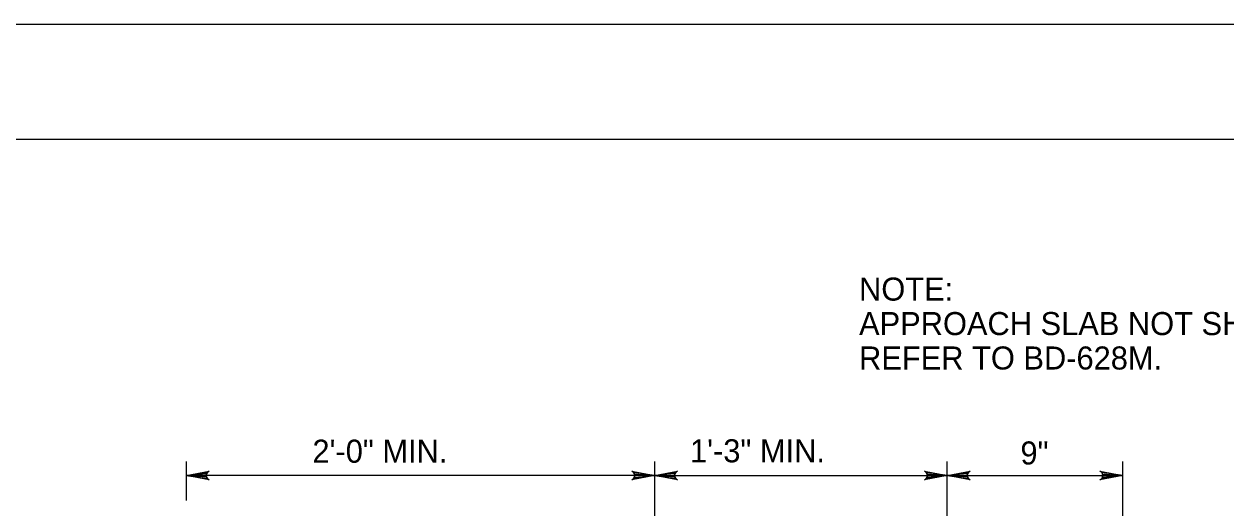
# Model space of a CAD drawing. Extents: x 640009 to 641706, y 298547 to 299735.
# Drawn here: x 640964.7 to 641121.1, y 299672.2 to 299735.2 of the extents above; entities that cross this region are included whole.
import ezdxf

# ---------------------------------------------------------------- set-up
doc = ezdxf.new("R2010")
doc.units = 0
doc.layers.add('1', color=7, linetype='Continuous')
doc.layers.add('PLT-BNDY', color=7, linetype='Continuous')

msp = doc.modelspace()

# ---------------------------------------------------------------- linework, layer by layer
at = {"layer": '1'}
for p, q in [((640890.47, 299720.17), (641676.47, 299720.17)), ((640890.47, 299720.17), (641676.47, 299720.17)), ((640985.78, 299678.22), (640985.78, 299673.16)), ((641046.74, 299678.22), (641046.74, 299655.13)), ((641084.84, 299649.2), (641084.84, 299678.22)), ((641107.7, 299669.52), (641107.7, 299678.22)), ((641046.74, 299676.42), (640985.78, 299676.42)), ((641046.74, 299676.42), (641084.84, 299676.42)), ((641084.84, 299676.42), (641107.7, 299676.42))]:
    msp.add_line(p, q, dxfattribs=at)
for points in [[(640985.78, 299676.42), (640988.77, 299676.98), (640988.54, 299676.82), (640988.42, 299676.62), (640988.38, 299676.42), (640988.42, 299676.22), (640988.54, 299676.02), (640988.77, 299675.86), (640985.78, 299676.42), (640988.54, 299676.02), (640988.42, 299676.22), (640985.78, 299676.42), (640988.38, 299676.42), (640988.42, 299676.62), (640985.78, 299676.42), (640988.54, 299676.82)], [(641046.74, 299676.42), (641043.76, 299675.86), (641043.99, 299676.02), (641044.11, 299676.22), (641044.14, 299676.42), (641044.11, 299676.62), (641043.99, 299676.82), (641043.76, 299676.98), (641046.74, 299676.42), (641043.99, 299676.82), (641044.11, 299676.62), (641046.74, 299676.42), (641044.14, 299676.42), (641044.11, 299676.22), (641046.74, 299676.42), (641043.99, 299676.02)], [(641046.74, 299676.42), (641049.73, 299676.98), (641049.5, 299676.82), (641049.38, 299676.62), (641049.34, 299676.42), (641049.38, 299676.22), (641049.5, 299676.02), (641049.73, 299675.86), (641046.74, 299676.42), (641049.5, 299676.02), (641049.38, 299676.22), (641046.74, 299676.42), (641049.34, 299676.42), (641049.38, 299676.62), (641046.74, 299676.42), (641049.5, 299676.82)], [(641084.84, 299676.42), (641081.86, 299675.86), (641082.09, 299676.02), (641082.21, 299676.22), (641082.24, 299676.42), (641082.21, 299676.62), (641082.09, 299676.82), (641081.86, 299676.98), (641084.84, 299676.42), (641082.09, 299676.82), (641082.21, 299676.62), (641084.84, 299676.42), (641082.24, 299676.42), (641082.21, 299676.22), (641084.84, 299676.42), (641082.09, 299676.02)], [(641084.84, 299676.42), (641087.83, 299676.98), (641087.6, 299676.82), (641087.48, 299676.62), (641087.44, 299676.42), (641087.48, 299676.22), (641087.6, 299676.02), (641087.83, 299675.86), (641084.84, 299676.42), (641087.6, 299676.02), (641087.48, 299676.22), (641084.84, 299676.42), (641087.44, 299676.42), (641087.48, 299676.62), (641084.84, 299676.42), (641087.6, 299676.82)], [(641107.7, 299676.42), (641104.72, 299675.86), (641104.95, 299676.02), (641105.07, 299676.22), (641105.1, 299676.42), (641105.07, 299676.62), (641104.95, 299676.82), (641104.72, 299676.98), (641107.7, 299676.42), (641104.95, 299676.82), (641105.07, 299676.62), (641107.7, 299676.42), (641105.1, 299676.42), (641105.07, 299676.22), (641107.7, 299676.42), (641104.95, 299676.02)]]:
    msp.add_lwpolyline(points, dxfattribs=at)
at = {"layer": 'PLT-BNDY'}
msp.add_lwpolyline([(640850.47, 299735.17), (641691.47, 299735.17), (641691.47, 299141.17), (640850.47, 299141.17)], close=True, dxfattribs=at)

# ---------------------------------------------------------------- texts
at = {"layer": '1'}
for s, p in [('NOTE:', (641073.36, 299699.18)), ('APPROACH SLAB NOT SHOWN,', (641073.36, 299694.69)), ('REFER TO BD-628M.', (641073.36, 299690.21)), ('2\'-0" MIN.', (641002.2, 299678.08)), ('1\'-3" MIN.', (641051.35, 299678.13)), ('9"', (641094.37, 299677.85))]:
    msp.add_text(s, height=3, dxfattribs=at).set_placement(p)

doc.saveas('drawing.dxf')
